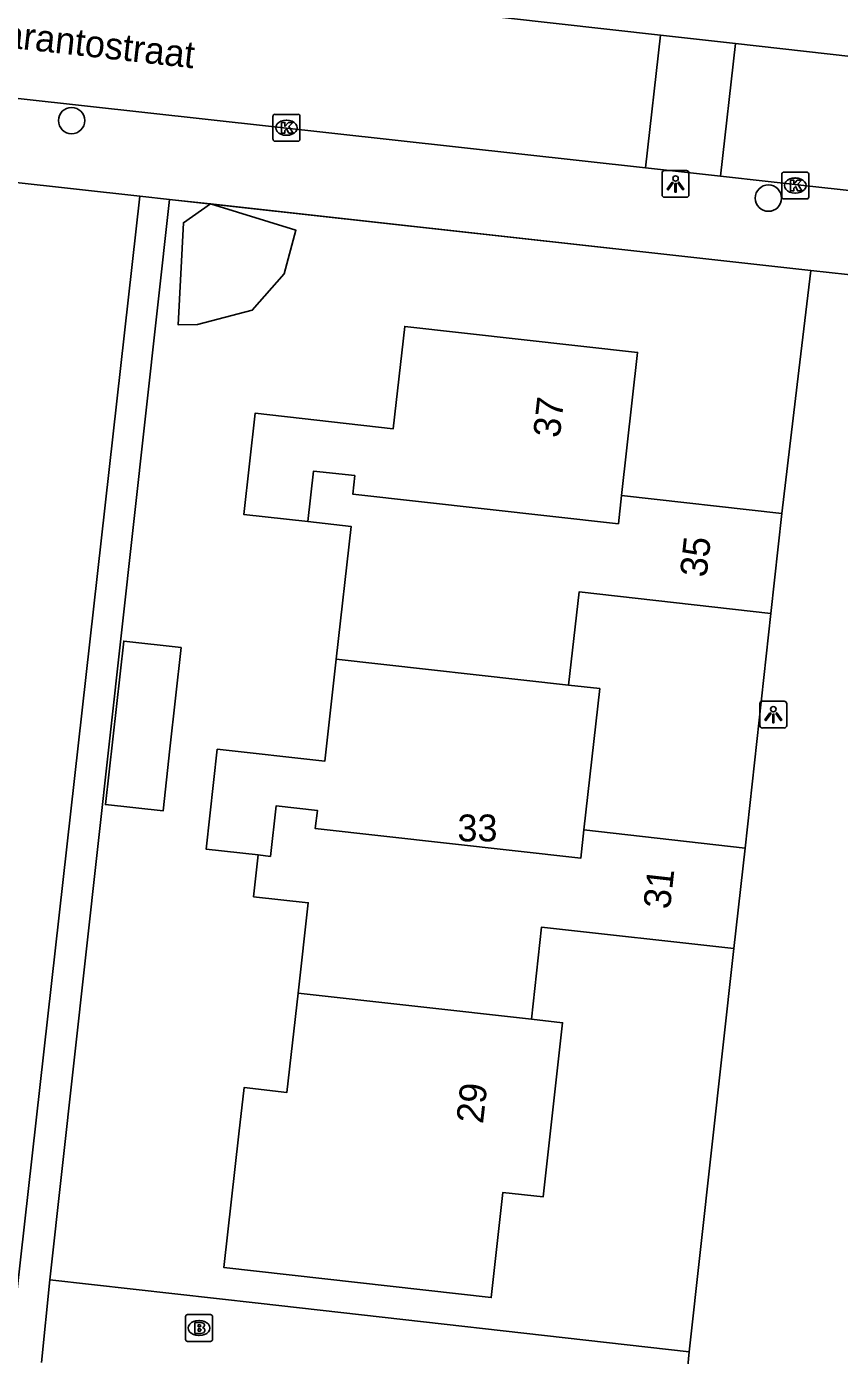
# Model space of a CAD drawing. Extents: x 162082 to 163393, y 388091 to 388632.
# Drawn here: x 162799.64 to 162829.85, y 388161.15 to 388210.56 of the extents above; entities that cross this region are included whole.
import ezdxf

# ---------------------------------------------------------------- set-up
doc = ezdxf.new("R2010")
doc.units = 0
for name, color, linetype in [('IMGEO_Boom', 7, 'Continuous'), ('IMGEO_Brandkraan', 7, 'Continuous'), ('IMGEO_Kolk', 7, 'Continuous'), ('IMGEO_Lichtpunt', 7, 'Continuous'), ('IMGEO_Muur', 7, 'Continuous'), ('IMGEO_Openbare_ruimte_label', 7, 'Continuous'), ('IMGEO_Pand', 7, 'Continuous'), ('IMGEO_Pand_nummerreeks', 7, 'Continuous'), ('IMGEO_Rijbaan_lokaal_open', 7, 'Continuous'), ('IMGEO_Voetpad_open', 7, 'Continuous')]:
    doc.layers.add(name, color=color, linetype=linetype)

msp = doc.modelspace()

# ---------------------------------------------------------------- linework, layer by layer
at = {"layer": 'IMGEO_Boom'}
for centre in [(162801.309, 388207.066), (162827.212, 388204.184)]:
    msp.add_circle(centre, 0.489, dxfattribs=at)
at = {"layer": 'IMGEO_Brandkraan'}
for p, q in [((162805.546, 388161.745), (162805.546, 388162.597)), ((162805.621, 388162.671), (162806.473, 388162.671)), ((162806.547, 388162.597), (162806.547, 388161.745)), ((162806.034, 388162.451), (162806.059, 388162.451)), ((162806.473, 388161.671), (162805.621, 388161.671)), ((162806.057, 388161.891), (162806.032, 388161.891))]:
    msp.add_line(p, q, dxfattribs=at)
for points in [[(162805.546, 388161.745), (162805.546, 388162.597)], [(162805.621, 388162.671), (162806.473, 388162.671)], [(162806.547, 388162.597), (162806.547, 388161.745)], [(162805.894, 388162.371), (162805.894, 388161.971), (162806.107, 388161.971)], [(162806.125, 388162.371), (162805.894, 388162.371)], [(162806.073, 388162.29), (162806.019, 388162.29), (162806.019, 388162.214)], [(162806.019, 388162.214), (162806.072, 388162.214)], [(162806.081, 388162.138), (162806.019, 388162.138), (162806.019, 388162.057)], [(162806.019, 388162.057), (162806.081, 388162.057)], [(162806.473, 388161.671), (162805.621, 388161.671)]]:
    msp.add_lwpolyline(points, dxfattribs=at)
for centre, radius, start, end in [((162805.623, 388162.595), 0.0765, 91.552, 178.448), ((162805.623, 388162.595), 0.0765, 91.552, 178.448), ((162806.471, 388162.595), 0.0765, 1.552, 88.448), ((162806.471, 388162.595), 0.0765, 1.552, 88.448), ((162806.074, 388162.252), 0.0379, 267.8285, 90.9355), ((162806.082, 388162.097), 0.0404, 269.8759, 90.5077), ((162806.129, 388162.226), 0.145, 59.4692, 91.5367), ((162806.154, 388162.273), 0.0922, 285.5137, 58.1501), ((162806.159, 388162.081), 0.105, 301.3115, 78.989), ((162805.623, 388161.747), 0.0765, 181.552, 268.448), ((162805.623, 388161.747), 0.0765, 181.552, 268.448), ((162806.113, 388162.222), 0.251, 268.6676, 293.5347), ((162806.471, 388161.747), 0.0765, 271.552, 358.448), ((162806.471, 388161.747), 0.0765, 271.552, 358.448)]:
    msp.add_arc(centre, radius, start, end, dxfattribs=at)
for centre, major_axis, ratio, start_param, end_param in [((162806.033, 388162.171), (-0.387, 0.002), 0.722429, 4.712389, 7.853982), ((162806.058, 388162.171), (-0.39, 0.002), 0.717154, 1.570796, 4.712389)]:
    msp.add_ellipse(centre, major_axis=major_axis, ratio=ratio, start_param=start_param, end_param=end_param, dxfattribs=at)
at = {"layer": 'IMGEO_Kolk'}
for p, q in [((162808.796, 388206.373), (162808.796, 388207.225)), ((162808.871, 388207.299), (162809.723, 388207.299)), ((162809.284, 388207.079), (162809.309, 388207.079)), ((162809.797, 388207.225), (162809.797, 388206.373)), ((162809.307, 388206.519), (162809.282, 388206.519)), ((162809.723, 388206.299), (162808.871, 388206.299)), ((162827.71, 388204.226), (162827.71, 388205.078)), ((162827.785, 388205.152), (162828.637, 388205.152)), ((162828.711, 388205.078), (162828.711, 388204.226)), ((162828.198, 388204.932), (162828.223, 388204.932)), ((162828.637, 388204.152), (162827.785, 388204.152)), ((162828.221, 388204.372), (162828.196, 388204.372))]:
    msp.add_line(p, q, dxfattribs=at)
for points in [[(162808.796, 388206.373), (162808.796, 388207.225)], [(162808.871, 388207.299), (162809.723, 388207.299)], [(162809.117, 388206.999), (162809.24, 388206.999), (162809.24, 388206.848), (162809.37, 388206.999), (162809.534, 388206.999), (162809.388, 388206.848), (162809.541, 388206.599), (162809.389, 388206.599), (162809.304, 388206.763), (162809.24, 388206.696), (162809.24, 388206.599), (162809.117, 388206.599), (162809.117, 388206.999)], [(162809.797, 388207.225), (162809.797, 388206.373)], [(162809.723, 388206.299), (162808.871, 388206.299)], [(162827.71, 388204.226), (162827.71, 388205.078)], [(162827.785, 388205.152), (162828.637, 388205.152)], [(162828.711, 388205.078), (162828.711, 388204.226)], [(162828.031, 388204.852), (162828.154, 388204.852), (162828.154, 388204.701), (162828.284, 388204.852), (162828.448, 388204.852), (162828.302, 388204.701), (162828.455, 388204.452), (162828.303, 388204.452), (162828.218, 388204.616), (162828.154, 388204.549), (162828.154, 388204.452), (162828.031, 388204.452), (162828.031, 388204.852)], [(162828.637, 388204.152), (162827.785, 388204.152)]]:
    msp.add_lwpolyline(points, dxfattribs=at)
for centre, start, end in [((162808.873, 388207.223), 91.552, 178.448), ((162808.873, 388207.223), 91.552, 178.448), ((162809.721, 388207.223), 1.552, 88.448), ((162809.721, 388207.223), 1.552, 88.448), ((162808.873, 388206.375), 181.552, 268.448), ((162808.873, 388206.375), 181.552, 268.448), ((162809.721, 388206.375), 271.552, 358.448), ((162809.721, 388206.375), 271.552, 358.448), ((162827.787, 388205.076), 91.552, 178.448), ((162827.787, 388205.076), 91.552, 178.448), ((162828.635, 388205.076), 1.552, 88.448), ((162828.635, 388205.076), 1.552, 88.448), ((162827.787, 388204.228), 181.552, 268.448), ((162827.787, 388204.228), 181.552, 268.448), ((162828.635, 388204.228), 271.552, 358.448), ((162828.635, 388204.228), 271.552, 358.448)]:
    msp.add_arc(centre, 0.0765, start, end, dxfattribs=at)
for centre, major_axis, ratio, start_param, end_param in [((162809.283, 388206.799), (-0.387, 0.002), 0.722429, 4.712389, 7.853982), ((162809.308, 388206.799), (-0.39, 0.002), 0.717154, 1.570796, 4.712389), ((162828.197, 388204.652), (-0.387, 0.002), 0.722429, 4.712389, 7.853982), ((162828.222, 388204.652), (-0.39, 0.002), 0.717154, 1.570796, 4.712389)]:
    msp.add_ellipse(centre, major_axis=major_axis, ratio=ratio, start_param=start_param, end_param=end_param, dxfattribs=at)
at = {"layer": 'IMGEO_Lichtpunt'}
for p, q in [((162823.262, 388205.116), (162823.262, 388204.309)), ((162823.262, 388205.116), (162823.262, 388204.309)), ((162824.164, 388205.211), (162823.356, 388205.211)), ((162824.164, 388205.211), (162823.356, 388205.211)), ((162824.258, 388204.309), (162824.258, 388205.116)), ((162824.258, 388204.309), (162824.258, 388205.116)), ((162823.356, 388204.215), (162824.164, 388204.215)), ((162823.356, 388204.215), (162824.164, 388204.215)), ((162826.897, 388185.383), (162826.897, 388184.576)), ((162826.897, 388185.383), (162826.897, 388184.576)), ((162827.799, 388185.478), (162826.991, 388185.478)), ((162827.799, 388185.478), (162826.991, 388185.478)), ((162827.893, 388184.576), (162827.893, 388185.383)), ((162827.893, 388184.576), (162827.893, 388185.383)), ((162826.991, 388184.482), (162827.799, 388184.482)), ((162826.991, 388184.482), (162827.799, 388184.482))]:
    msp.add_line(p, q, dxfattribs=at)
for points in [[(162823.636, 388204.78), (162823.675, 388204.752), (162823.487, 388204.49), (162823.449, 388204.517), (162823.636, 388204.78)], [(162823.738, 388204.732), (162823.785, 388204.732), (162823.785, 388204.41), (162823.738, 388204.41), (162823.738, 388204.732)], [(162823.848, 388204.752), (162823.886, 388204.779), (162824.073, 388204.517), (162824.034, 388204.489), (162823.848, 388204.752)], [(162827.271, 388185.047), (162827.31, 388185.019), (162827.122, 388184.757), (162827.084, 388184.784), (162827.271, 388185.047)], [(162827.373, 388184.999), (162827.42, 388184.999), (162827.42, 388184.677), (162827.373, 388184.677), (162827.373, 388184.999)], [(162827.483, 388185.019), (162827.521, 388185.046), (162827.708, 388184.784), (162827.669, 388184.756), (162827.483, 388185.019)]]:
    msp.add_lwpolyline(points, dxfattribs=at)
for centre in [(162823.761, 388204.914), (162827.396, 388185.181)]:
    msp.add_circle(centre, 0.0994, dxfattribs=at)
for centre, start, end in [((162823.356, 388205.116), 90, 180), ((162823.356, 388205.116), 90, 180), ((162824.164, 388205.116), 0, 90), ((162824.164, 388205.116), 0, 90), ((162823.356, 388204.309), 180, 270), ((162823.356, 388204.309), 180, 270), ((162824.164, 388204.309), 270, 0), ((162824.164, 388204.309), 270, 360), ((162826.991, 388185.383), 90, 180), ((162826.991, 388185.383), 90, 180), ((162827.799, 388185.383), 0, 90), ((162827.799, 388185.383), 0, 90), ((162826.991, 388184.576), 180, 270), ((162826.991, 388184.576), 180, 270), ((162827.799, 388184.576), 270, 0), ((162827.799, 388184.576), 270, 360)]:
    msp.add_arc(centre, 0.0946, start, end, dxfattribs=at)
at = {"layer": 'IMGEO_Muur'}
for points in [[(162822.766, 388202.163), (162805.174, 388204.111)], [(162800.498, 388163.968), (162808.249, 388163.092)]]:
    msp.add_lwpolyline(points, dxfattribs=at)
at = {"layer": 'IMGEO_Pand'}
for points in [[(162806.47, 388203.971), (162809.648, 388202.99), (162809.21, 388201.37), (162808.027, 388200.015), (162805.985, 388199.48), (162805.271, 388199.468), (162805.463, 388203.267), (162806.47, 388203.971)], [(162810.096, 388192.157), (162807.706, 388192.425), (162808.127, 388196.187), (162813.265, 388195.611), (162813.691, 388199.414), (162822.35, 388198.445), (162821.754, 388193.126)], [(162810.096, 388192.157), (162810.306, 388194.035), (162811.838, 388193.864), (162811.76, 388193.182), (162821.636, 388192.076), (162821.754, 388193.126)], [(162821.754, 388193.126), (162827.717, 388192.459)], [(162827.301, 388188.741), (162827.717, 388192.459)], [(162811.144, 388187.047), (162811.696, 388191.978), (162810.096, 388192.157)], [(162819.787, 388186.08), (162820.174, 388189.539), (162827.301, 388188.741)], [(162805.388, 388187.474), (162804.966, 388183.706), (162804.707, 388181.397), (162802.567, 388181.636), (162803.248, 388187.714), (162805.388, 388187.474)], [(162808.25, 388179.76), (162806.307, 388179.977), (162806.723, 388183.693), (162810.718, 388183.246), (162811.144, 388187.047)], [(162819.787, 388186.08), (162811.144, 388187.047)], [(162820.357, 388180.689), (162820.946, 388185.95), (162819.787, 388186.08)], [(162820.357, 388180.689), (162820.239, 388179.637), (162810.368, 388180.742), (162810.446, 388181.418), (162808.914, 388181.589), (162808.703, 388179.709), (162808.25, 388179.76)], [(162826.346, 388180.019), (162820.357, 388180.689)], [(162825.928, 388176.279), (162826.346, 388180.019)], [(162809.728, 388174.626), (162810.104, 388177.982), (162808.077, 388178.209), (162808.25, 388179.76)], [(162825.928, 388176.279), (162818.783, 388177.079), (162818.4, 388173.653)], [(162818.4, 388173.653), (162819.561, 388173.523), (162818.835, 388167.043), (162817.345, 388167.21), (162816.908, 388163.305), (162806.971, 388164.418), (162807.527, 388169.387), (162807.72, 388171.109), (162809.314, 388170.93), (162809.728, 388174.626)], [(162809.728, 388174.626), (162818.4, 388173.653)]]:
    msp.add_lwpolyline(points, dxfattribs=at)
at = {"layer": 'IMGEO_Rijbaan_lokaal_open'}
for points in [[(162823.2, 388210.24), (162784.632, 388214.568)], [(162822.64, 388205.309), (162823.2, 388210.24)], [(162823.2, 388210.24), (162825.987, 388209.927)], [(162825.427, 388205), (162825.987, 388209.927)], [(162825.987, 388209.927), (162834.672, 388208.952)], [(162822.64, 388205.309), (162785.514, 388209.412)], [(162825.427, 388205), (162822.64, 388205.309)], [(162883.87, 388198.497), (162873.136, 388199.708), (162869.36, 388200.134), (162864.571, 388200.674), (162851.342, 388202.136), (162843.421, 388203.012), (162836.753, 388203.749), (162828.977, 388204.608), (162825.427, 388205)], [(162827.717, 388192.459), (162828.347, 388197.774), (162828.788, 388201.496)], [(162828.788, 388201.496), (162850.603, 388199.107)], [(162827.301, 388188.741), (162826.346, 388180.019)], [(162824.27, 388161.282), (162825.928, 388176.279)], [(162823.979, 388158.253), (162824.27, 388161.282)]]:
    msp.add_lwpolyline(points, dxfattribs=at)
at = {"layer": 'IMGEO_Voetpad_open'}
for points in [[(162803.844, 388204.258), (162784.556, 388206.394)], [(162786.901, 388135.177), (162795.979, 388134.212), (162803.844, 388204.258)], [(162804.95, 388204.136), (162800.498, 388163.968)], [(162803.844, 388204.258), (162804.95, 388204.136)], [(162806.47, 388203.971), (162805.174, 388204.111), (162804.95, 388204.136)], [(162828.788, 388201.496), (162822.766, 388202.163), (162806.47, 388203.971)], [(162800.192, 388160.886), (162800.498, 388163.968)], [(162800.498, 388163.968), (162808.249, 388163.092), (162824.27, 388161.282)]]:
    msp.add_lwpolyline(points, dxfattribs=at)

# ---------------------------------------------------------------- texts
at = {"layer": 'IMGEO_Openbare_ruimte_label'}
msp.add_text('Tarantostraat', height=1, rotation=353.6282, dxfattribs=at).set_placement((162797.923, 388209.893))
at = {"layer": 'IMGEO_Pand_nummerreeks'}
for s, rotation, p in [('37', 83.6066, (162819.455, 388195.245)), ('35', 83.6158, (162824.912, 388190.059)), ('31', 83.6232, (162823.553, 388177.72)), ('29', 83.6074, (162816.601, 388169.743))]:
    msp.add_text(s, height=1, rotation=rotation, dxfattribs=at).set_placement(p)
msp.add_text('33', height=1, dxfattribs=at).set_placement((162815.654, 388180.264))

doc.saveas('drawing.dxf')
